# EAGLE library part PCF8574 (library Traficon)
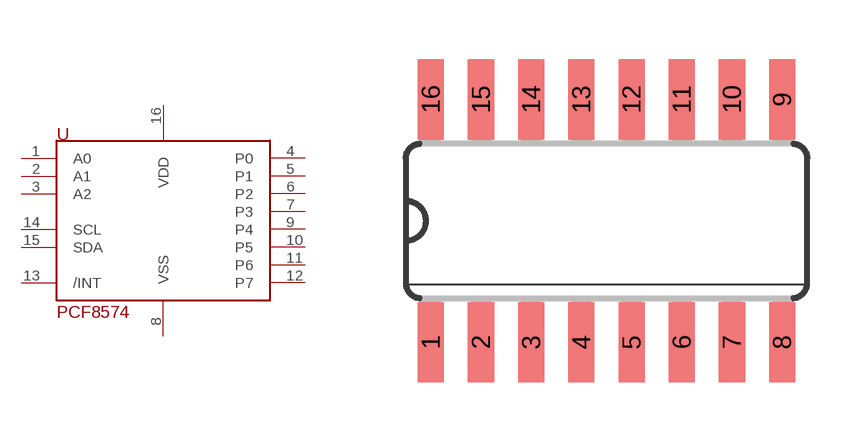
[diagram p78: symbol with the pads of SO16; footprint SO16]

Designator prefix U

## PCF8574  [SO16]
1  A0  in
2  A1  in
3  A2  in
4  P0
5  P1
6  P2
7  P3
8  VSS  pwr
9  P4
10  P5
11  P6
12  P7
13  /INT  out
14  SCL  in
15  SDA
16  VDD  pwr

## Footprint SO16 (pad centres in mm)
Small Outline package 150 mil
smd 0.66 x 2.032: 1 -4.445,-3.073; 2 -3.175,-3.073; 3 -1.905,-3.073; 4 -0.635,-3.073; 5 0.635,-3.073; 6 1.905,-3.073; 7 3.175,-3.073; 8 4.445,-3.073; 9 4.445,3.073; 10 3.175,3.073; 11 1.905,3.073; 12 0.635,3.073; 13 -0.635,3.073; 14 -1.905,3.073; 15 -3.175,3.073; 16 -4.445,3.073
